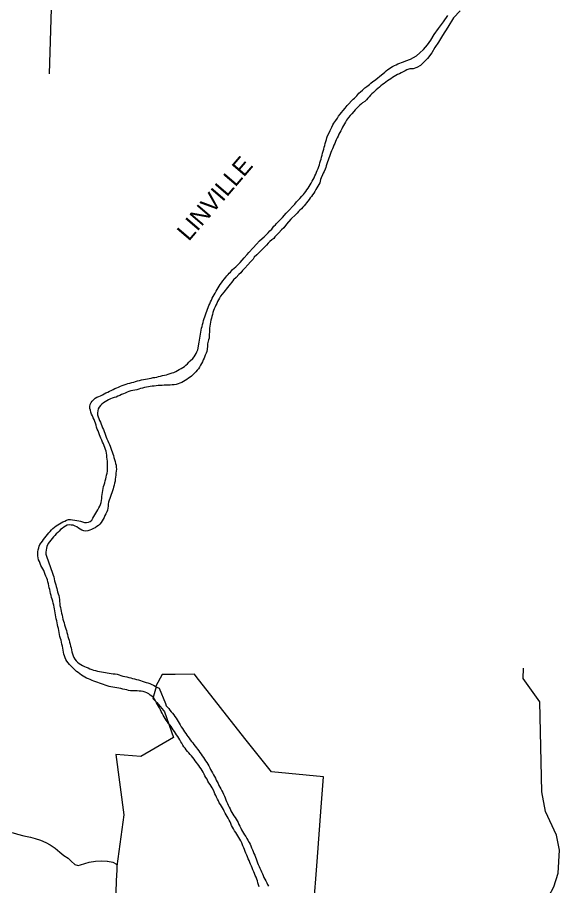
# Model space of a CAD drawing. Extents: x 1113032 to 1302912, y 664689 to 832535.
# Drawn here: x 1135345 to 1141854, y 765901 to 776333 of the extents above; entities that cross this region are included whole.
import ezdxf

# ---------------------------------------------------------------- set-up
doc = ezdxf.new("R2010")
doc.units = 0
for name, color, linetype in [('Exist Boundary Land Use Forest National US Forest Service', 7, 'Continuous'), ('Exist Hydrographic Creek Single Shore', 7, 'Continuous'), ('Exist Hydrographic River Shore', 7, 'Continuous'), ('Exist Hydrographic River Shore Label', 7, 'Continuous'), ('Map Preparation Longitude Latitude Lines', 7, 'Continuous')]:
    doc.layers.add(name, color=color, linetype=linetype)

msp = doc.modelspace()

# ---------------------------------------------------------------- linework, layer by layer
at = {"layer": 'Exist Boundary Land Use Forest National US Forest Service'}
for points in [[(1138713, 763223), (1138723, 763348), (1138943, 766193), (1138993, 766844), (1139021, 767208), (1138394, 767267), (1138077, 767670), (1137491, 768414), (1137470, 768440), (1137238, 768439), (1137082, 768438), (1137008, 768296), (1137011, 768288), (1136972, 768151), (1137018, 768103), (1137101, 768007), (1137113, 767991), (1137220, 767682), (1136825, 767454), (1136525, 767475), (1136621, 766751), (1136539, 766137)], [(1135282, 766541), (1135348, 766518), (1135421, 766500), (1135503, 766483), (1135560, 766467), (1135624, 766449), (1135687, 766421), (1135740, 766390), (1135797, 766350), (1135855, 766304), (1135904, 766264), (1135953, 766231), (1135990, 766197), (1136034, 766154), (1136076, 766145), (1136104, 766152), (1136153, 766166), (1136207, 766182), (1136284, 766194), (1136352, 766198), (1136424, 766195), (1136426, 766195), (1136492, 766183), (1136533, 766158), (1136539, 766137)], [(1136539, 766137), (1136539, 766090), (1136530, 765960), (1136513, 765408), (1136497, 764754), (1136478, 764256), (1136446, 763434), (1136733, 763409), (1136853, 763399), (1137087, 763379), (1137787, 763312), (1138068, 763285), (1138186, 763274), (1138552, 763238), (1138713, 763223)]]:
    msp.add_lwpolyline(points, dxfattribs=at)
at = {"layer": 'Exist Hydrographic Creek Single Shore'}
msp.add_lwpolyline([(1140069, 761301), (1140449, 761951), (1140862, 762655), (1141048, 763042), (1141122, 763273), (1141016, 763659), (1140714, 764161), (1140645, 764353), (1140664, 764720), (1140725, 764811), (1140922, 764964), (1141070, 765191), (1141182, 765297), (1141538, 765487), (1141606, 765551), (1141783, 765889), (1141838, 766052), (1141854, 766328), (1141818, 766506), (1141685, 766791), (1141641, 767028), (1141615, 768111), (1141415, 768391), (1141419, 768516)], dxfattribs=at)
at = {"layer": 'Exist Hydrographic River Shore'}
for points in [[(1140661, 776411), (1140582, 776328), (1140512, 776216), (1140449, 776116), (1140400, 776034), (1140358, 775970), (1140319, 775908), (1140267, 775838), (1140222, 775790), (1140183, 775755), (1140142, 775730), (1140096, 775715), (1140057, 775714), (1140022, 775704), (1140000, 775691), (1139952, 775667), (1139931, 775656), (1139909, 775645), (1139888, 775633), (1139868, 775621), (1139847, 775609), (1139827, 775596), (1139807, 775582), (1139787, 775569), (1139767, 775555), (1139747, 775540), (1139728, 775525), (1139709, 775510), (1139691, 775495), (1139672, 775479), (1139654, 775463), (1139636, 775447), (1139619, 775430), (1139602, 775414), (1139585, 775396), (1139568, 775379), (1139552, 775361), (1139536, 775343), (1139516, 775323), (1139489, 775304), (1139474, 775292), (1139454, 775277), (1139439, 775262), (1139421, 775242), (1139398, 775220), (1139383, 775202), (1139358, 775175), (1139338, 775153)], [(1139028, 774772), (1139035, 774795), (1139041, 774818), (1139048, 774841), (1139055, 774864), (1139061, 774887), (1139068, 774910), (1139086, 774947), (1139100, 774973), (1139118, 775012), (1139133, 775042), (1139144, 775061), (1139168, 775095), (1139186, 775121), (1139200, 775147), (1139219, 775170), (1139235, 775191), (1139255, 775214), (1139279, 775240), (1139305, 775273), (1139320, 775289), (1139358, 775332), (1139376, 775348), (1139390, 775360), (1139418, 775389), (1139445, 775420), (1139463, 775438), (1139487, 775459), (1139515, 775485), (1139539, 775502), (1139557, 775514), (1139573, 775527), (1139588, 775541), (1139614, 775562), (1139632, 775576), (1139667, 775604), (1139695, 775625), (1139733, 775655), (1139755, 775675), (1139773, 775691), (1139791, 775706), (1139811, 775719), (1139830, 775731), (1139850, 775742), (1139871, 775753), (1139892, 775763), (1139914, 775773), (1139935, 775782), (1139957, 775791), (1139980, 775799), (1140010, 775810), (1140066, 775830), (1140101, 775849), (1140138, 775871), (1140178, 775905), (1140221, 775947), (1140267, 776003), (1140310, 776058), (1140348, 776125), (1140401, 776198), (1140461, 776278), (1140514, 776353)], [(1139338, 775153), (1139321, 775128), (1139297, 775096), (1139285, 775075), (1139273, 775055), (1139261, 775034), (1139249, 775013), (1139238, 774992), (1139227, 774971), (1139216, 774949), (1139205, 774928), (1139194, 774906), (1139184, 774885), (1139173, 774863), (1139163, 774841), (1139154, 774819), (1139144, 774797), (1139135, 774775), (1139126, 774753), (1139117, 774731), (1139108, 774709), (1139099, 774686), (1139091, 774663), (1139083, 774641), (1139075, 774618), (1139068, 774595), (1139060, 774573), (1139053, 774550), (1139046, 774527), (1139041, 774507), (1139026, 774479), (1139017, 774460), (1139006, 774441), (1138993, 774403), (1138985, 774386), (1138981, 774364), (1138974, 774346), (1138963, 774325), (1138951, 774304), (1138940, 774283), (1138927, 774263), (1138915, 774242), (1138902, 774222), (1138889, 774202), (1138875, 774182), (1138861, 774163), (1138847, 774143), (1138832, 774124), (1138817, 774105), (1138802, 774087), (1138786, 774069), (1138770, 774051), (1138754, 774033), (1138737, 774016), (1138720, 773999), (1138703, 773982), (1138687, 773966), (1138629, 773908), (1138577, 773847), (1138542, 773806), (1138517, 773779), (1138484, 773743), (1138457, 773717), (1138437, 773694), (1138424, 773677), (1138401, 773659), (1138376, 773638), (1138357, 773619), (1138335, 773594), (1138309, 773569), (1138262, 773525), (1138218, 773481), (1138189, 773453), (1138174, 773429), (1138145, 773397), (1138112, 773361), (1138077, 773321), (1138049, 773291), (1138028, 773263), (1138005, 773242), (1137970, 773209), (1137939, 773181), (1137918, 773153), (1137901, 773129), (1137866, 773086), (1137824, 773033), (1137783, 772982), (1137771, 772961), (1137759, 772940), (1137748, 772919), (1137738, 772897), (1137727, 772876), (1137718, 772854), (1137709, 772831), (1137701, 772809), (1137693, 772786), (1137686, 772763), (1137680, 772740), (1137674, 772717), (1137668, 772693)], [(1137498, 772314), (1137511, 772338), (1137529, 772431), (1137532, 772455), (1137535, 772479), (1137539, 772502), (1137543, 772526), (1137547, 772550), (1137552, 772573), (1137557, 772597), (1137563, 772620), (1137568, 772643), (1137575, 772666), (1137581, 772690), (1137588, 772713), (1137595, 772735), (1137602, 772758), (1137610, 772781), (1137618, 772804), (1137627, 772826), (1137636, 772848), (1137645, 772871), (1137654, 772893), (1137664, 772914), (1137674, 772936), (1137685, 772958), (1137696, 772979), (1137707, 773000), (1137718, 773021), (1137730, 773042), (1137742, 773063), (1137755, 773084), (1137767, 773104), (1137780, 773124), (1137794, 773144), (1137810, 773167), (1137830, 773193), (1137847, 773212), (1137861, 773226), (1137876, 773243), (1137888, 773258), (1137903, 773273), (1137929, 773302), (1137947, 773318), (1137967, 773336), (1137991, 773358), (1138018, 773386), (1138043, 773415), (1138067, 773442), (1138105, 773484), (1138125, 773508), (1138176, 773562), (1138215, 773606), (1138250, 773646), (1138283, 773675), (1138308, 773697), (1138329, 773717), (1138356, 773743), (1138377, 773767), (1138401, 773790), (1138424, 773824), (1138442, 773842), (1138456, 773856), (1138489, 773890), (1138527, 773930), (1138573, 773980), (1138611, 774019), (1138646, 774059), (1138675, 774090), (1138697, 774115), (1138714, 774135), (1138734, 774156), (1138760, 774186), (1138780, 774204), (1138793, 774222), (1138807, 774241), (1138821, 774261), (1138834, 774281), (1138847, 774301), (1138860, 774322), (1138872, 774342), (1138884, 774363), (1138895, 774385), (1138906, 774406), (1138916, 774428), (1138926, 774450), (1138936, 774472), (1138945, 774494), (1138954, 774516), (1138962, 774539), (1138970, 774561), (1138977, 774584), (1138984, 774607), (1138990, 774630), (1138996, 774654), (1139003, 774679), (1139009, 774702), (1139016, 774725), (1139022, 774748), (1139028, 774772)], [(1137668, 772693), (1137664, 772670), (1137660, 772646), (1137656, 772622), (1137653, 772599)], [(1137653, 772599), (1137651, 772575), (1137650, 772551), (1137649, 772527), (1137649, 772503), (1137649, 772479), (1137641, 772460), (1137634, 772443), (1137629, 772411), (1137626, 772382), (1137622, 772348), (1137618, 772317), (1137611, 772300), (1137599, 772273), (1137586, 772239), (1137577, 772217), (1137567, 772195), (1137556, 772173), (1137544, 772153), (1137532, 772132), (1137518, 772112), (1137503, 772093), (1137488, 772075), (1137472, 772057), (1137455, 772041), (1137437, 772024), (1137421, 772011), (1137401, 771997), (1137381, 771983), (1137361, 771970), (1137340, 771958), (1137319, 771947), (1137296, 771939), (1137274, 771930), (1137251, 771923), (1137227, 771919), (1137204, 771916), (1137180, 771912), (1137156, 771912), (1137132, 771913), (1137108, 771913), (1137084, 771911), (1137060, 771909), (1137036, 771908), (1137012, 771905), (1136988, 771902), (1136964, 771900), (1136940, 771898), (1136917, 771894), (1136893, 771890), (1136870, 771884), (1136847, 771878), (1136824, 771872), (1136801, 771865), (1136777, 771859), (1136754, 771853), (1136730, 771849), (1136707, 771844), (1136684, 771837), (1136662, 771828), (1136639, 771819), (1136617, 771809), (1136595, 771800), (1136573, 771790), (1136552, 771780), (1136530, 771770), (1136507, 771764), (1136484, 771756), (1136461, 771748), (1136440, 771736), (1136419, 771725), (1136398, 771714), (1136378, 771701), (1136358, 771687), (1136341, 771670), (1136327, 771651), (1136315, 771630), (1136309, 771606), (1136306, 771583), (1136308, 771559), (1136313, 771535), (1136321, 771513), (1136331, 771491), (1136341, 771469), (1136349, 771446), (1136358, 771424), (1136367, 771402), (1136377, 771380), (1136386, 771358), (1136395, 771336), (1136403, 771313), (1136411, 771290), (1136420, 771268), (1136430, 771246), (1136440, 771225), (1136450, 771203), (1136459, 771180), (1136468, 771158), (1136476, 771135), (1136483, 771113)], [(1136410, 770810), (1136416, 770834), (1136421, 770857), (1136425, 770881), (1136427, 770905), (1136428, 770929), (1136428, 770953), (1136427, 770977), (1136425, 771001), (1136423, 771024), (1136420, 771048), (1136418, 771072), (1136414, 771096), (1136410, 771120), (1136404, 771143), (1136395, 771165), (1136386, 771187), (1136377, 771209), (1136367, 771231), (1136358, 771254), (1136348, 771276), (1136338, 771297), (1136329, 771319), (1136321, 771342), (1136313, 771365), (1136304, 771387), (1136296, 771409), (1136289, 771433), (1136283, 771456), (1136275, 771478), (1136266, 771501), (1136256, 771523), (1136246, 771544), (1136236, 771566), (1136228, 771589), (1136221, 771612), (1136216, 771635), (1136215, 771659), (1136217, 771683), (1136229, 771704), (1136244, 771722), (1136261, 771740), (1136279, 771756), (1136299, 771768), (1136321, 771777), (1136343, 771787), (1136365, 771798), (1136386, 771809), (1136407, 771820), (1136429, 771831), (1136450, 771841), (1136472, 771851), (1136493, 771862), (1136515, 771874), (1136537, 771883), (1136559, 771891), (1136581, 771900), (1136603, 771910), (1136626, 771917), (1136649, 771925), (1136672, 771932), (1136695, 771939), (1136718, 771945), (1136741, 771951), (1136764, 771958), (1136787, 771965), (1136810, 771970), (1136834, 771976), (1136857, 771980), (1136881, 771984), (1136905, 771988), (1136928, 771993), (1136951, 772000), (1136975, 772005), (1136994, 772008), (1137017, 772012), (1137040, 772018), (1137064, 772023), (1137087, 772029), (1137110, 772034), (1137134, 772040), (1137157, 772046), (1137180, 772054), (1137203, 772061), (1137225, 772068), (1137247, 772078), (1137268, 772090), (1137289, 772102), (1137310, 772114), (1137331, 772126), (1137350, 772140), (1137369, 772155), (1137386, 772172), (1137403, 772189), (1137419, 772206), (1137450, 772233), (1137467, 772255), (1137479, 772276), (1137492, 772296), (1137498, 772314)], [(1136483, 771113), (1136491, 771090), (1136498, 771067), (1136504, 771044), (1136510, 771020), (1136517, 770997), (1136523, 770974), (1136529, 770951), (1136531, 770927), (1136533, 770903), (1136531, 770879), (1136528, 770855), (1136526, 770832), (1136523, 770808), (1136520, 770784), (1136517, 770760), (1136512, 770737), (1136506, 770713), (1136500, 770690), (1136494, 770667), (1136486, 770644), (1136479, 770621), (1136471, 770599), (1136464, 770576), (1136456, 770553), (1136446, 770532), (1136439, 770508), (1136436, 770485), (1136434, 770461), (1136431, 770437), (1136425, 770414), (1136418, 770391), (1136408, 770369), (1136396, 770348), (1136386, 770326), (1136375, 770305), (1136363, 770284), (1136350, 770264), (1136335, 770245), (1136317, 770229), (1136298, 770214), (1136278, 770201), (1136257, 770190), (1136235, 770179), (1136213, 770170), (1136190, 770163), (1136166, 770161), (1136142, 770164), (1136120, 770173), (1136098, 770182), (1136079, 770197), (1136059, 770210), (1136037, 770220), (1136016, 770230), (1135991, 770233), (1135967, 770234), (1135944, 770230), (1135922, 770220), (1135901, 770208), (1135881, 770193), (1135863, 770178), (1135846, 770161), (1135829, 770144), (1135812, 770127), (1135794, 770109), (1135777, 770091), (1135761, 770072), (1135745, 770053), (1135730, 770033), (1135716, 770013), (1135700, 769977), (1135693, 769954), (1135689, 769930), (1135686, 769906), (1135688, 769882), (1135695, 769859), (1135704, 769837), (1135712, 769814), (1135720, 769792), (1135728, 769769), (1135735, 769746), (1135743, 769724), (1135750, 769701), (1135757, 769678), (1135765, 769655), (1135774, 769633), (1135781, 769610), (1135785, 769586), (1135790, 769563), (1135798, 769540), (1135805, 769517), (1135811, 769494), (1135818, 769471), (1135823, 769452), (1135828, 769432), (1135835, 769409), (1135841, 769386), (1135846, 769363), (1135849, 769339), (1135852, 769315)], [(1136388, 770717), (1136394, 770740), (1136399, 770764), (1136405, 770787), (1136410, 770810)], [(1135863, 768872), (1135856, 768895), (1135851, 768919), (1135846, 768942), (1135842, 768966), (1135837, 768990), (1135832, 769013), (1135827, 769036), (1135822, 769060), (1135817, 769083), (1135812, 769107), (1135808, 769130), (1135803, 769154), (1135798, 769177), (1135794, 769201), (1135791, 769225), (1135786, 769248), (1135781, 769272), (1135775, 769295), (1135769, 769318), (1135762, 769341), (1135756, 769364), (1135749, 769388), (1135743, 769411), (1135738, 769435), (1135733, 769458), (1135728, 769481), (1135724, 769505), (1135719, 769528), (1135712, 769551), (1135705, 769574), (1135697, 769597), (1135687, 769618), (1135679, 769641), (1135671, 769664), (1135661, 769686), (1135649, 769707), (1135638, 769728), (1135628, 769749), (1135618, 769771), (1135609, 769794), (1135600, 769816), (1135594, 769839), (1135590, 769863), (1135589, 769887), (1135591, 769911), (1135596, 769934), (1135602, 769958), (1135608, 769981), (1135615, 769999), (1135631, 770019), (1135645, 770038), (1135659, 770060), (1135674, 770081), (1135689, 770101), (1135705, 770121), (1135722, 770139), (1135739, 770157), (1135755, 770175), (1135771, 770192), (1135789, 770209), (1135809, 770222), (1135829, 770235), (1135849, 770248), (1135869, 770261), (1135891, 770272), (1135913, 770281), (1135935, 770291), (1135957, 770300), (1135981, 770299), (1136005, 770295), (1136034, 770292), (1136057, 770289), (1136081, 770285), (1136104, 770279), (1136127, 770271), (1136151, 770266), (1136175, 770266), (1136199, 770268), (1136220, 770278), (1136238, 770294), (1136250, 770315), (1136261, 770336), (1136273, 770357), (1136285, 770378), (1136298, 770398), (1136311, 770418), (1136322, 770439), (1136336, 770459), (1136344, 770482), (1136350, 770505), (1136354, 770529), (1136357, 770552), (1136359, 770576), (1136362, 770600), (1136366, 770624), (1136370, 770648), (1136374, 770671), (1136379, 770695), (1136388, 770717)], [(1135852, 769315), (1135854, 769291), (1135856, 769267), (1135861, 769244), (1135867, 769220), (1135872, 769197), (1135876, 769173), (1135881, 769150), (1135887, 769126), (1135892, 769103), (1135898, 769080), (1135905, 769057), (1135912, 769034), (1135919, 769011), (1135927, 768988), (1135933, 768965), (1135940, 768942), (1135945, 768919), (1135950, 768895), (1135957, 768872), (1135965, 768850), (1135972, 768826), (1135978, 768803), (1135984, 768780), (1135989, 768757), (1135995, 768733), (1136000, 768710), (1136005, 768686), (1136013, 768664), (1136022, 768642), (1136035, 768621), (1136051, 768603), (1136068, 768586), (1136086, 768571), (1136106, 768557), (1136127, 768545), (1136149, 768536), (1136171, 768527), (1136193, 768517), (1136215, 768507), (1136237, 768498), (1136260, 768490), (1136283, 768484), (1136306, 768478), (1136330, 768474), (1136354, 768470), (1136378, 768467), (1136401, 768462), (1136424, 768456), (1136448, 768452), (1136472, 768449), (1136496, 768447), (1136520, 768445), (1136543, 768442), (1136566, 768435), (1136588, 768426), (1136611, 768419), (1136635, 768414), (1136658, 768408), (1136681, 768402), (1136705, 768396), (1136728, 768390), (1136751, 768384), (1136775, 768378), (1136798, 768373), (1136821, 768365), (1136843, 768357), (1136866, 768350), (1136889, 768343), (1136912, 768336), (1136935, 768328), (1136957, 768319), (1136979, 768309), (1137000, 768298), (1137020, 768285), (1137048, 768272), (1137122, 768088), (1137133, 768063), (1137148, 768047), (1137162, 768028), (1137177, 768009), (1137193, 767990), (1137208, 767972), (1137222, 767953), (1137237, 767933), (1137250, 767914), (1137263, 767894), (1137276, 767873), (1137288, 767852), (1137300, 767832), (1137313, 767811), (1137326, 767791), (1137340, 767771), (1137353, 767751), (1137366, 767731), (1137379, 767711), (1137393, 767692), (1137407, 767672), (1137421, 767653), (1137436, 767634)], [(1137494, 767382), (1137480, 767402), (1137466, 767422), (1137451, 767441), (1137436, 767459), (1137421, 767478), (1137405, 767496), (1137389, 767514), (1137373, 767532), (1137358, 767551), (1137345, 767570), (1137331, 767590), (1137319, 767611), (1137307, 767631), (1137295, 767653), (1137283, 767673), (1137270, 767694), (1137257, 767714), (1137243, 767733), (1137230, 767753), (1137217, 767773), (1137204, 767794), (1137191, 767814), (1137177, 767833), (1137161, 767851), (1137146, 767870), (1137132, 767889), (1137118, 767909), (1137107, 767930), (1137095, 767951), (1137084, 767972), (1137072, 767994), (1137062, 768015), (1137052, 768037), (1137039, 768057), (1137027, 768078), (1137016, 768099), (1137004, 768120), (1136992, 768141), (1136977, 768160), (1136959, 768176), (1136940, 768191), (1136922, 768206), (1136900, 768216), (1136878, 768224), (1136855, 768232), (1136831, 768237), (1136807, 768239), (1136784, 768241), (1136752, 768242), (1136727, 768242), (1136703, 768243), (1136680, 768247), (1136657, 768253), (1136633, 768259), (1136610, 768263), (1136586, 768268), (1136563, 768273), (1136539, 768277), (1136516, 768282), (1136492, 768285), (1136468, 768289), (1136445, 768295), (1136422, 768302), (1136399, 768309), (1136377, 768318), (1136354, 768325), (1136331, 768333), (1136309, 768342), (1136286, 768350), (1136264, 768359), (1136241, 768367), (1136219, 768376), (1136197, 768385), (1136175, 768395), (1136154, 768405), (1136133, 768418), (1136113, 768431), (1136093, 768445), (1136074, 768460), (1136056, 768475), (1136038, 768491), (1136021, 768508), (1136004, 768525), (1135988, 768543), (1135971, 768560), (1135955, 768578), (1135940, 768597), (1135927, 768617), (1135917, 768639), (1135909, 768661), (1135902, 768684), (1135897, 768708), (1135893, 768732), (1135889, 768755), (1135885, 768779), (1135880, 768802), (1135875, 768826), (1135869, 768849), (1135863, 768872)], [(1137436, 767634), (1137450, 767615), (1137465, 767596), (1137480, 767577), (1137494, 767558), (1137509, 767539), (1137523, 767519), (1137537, 767500), (1137551, 767481), (1137565, 767461), (1137579, 767441), (1137592, 767421), (1137605, 767401), (1137619, 767381), (1137631, 767361), (1137643, 767339), (1137654, 767318), (1137665, 767297), (1137677, 767276), (1137688, 767255), (1137700, 767234), (1137711, 767213), (1137722, 767191), (1137732, 767170), (1137743, 767148), (1137754, 767127), (1137765, 767105), (1137776, 767084), (1137788, 767063), (1137800, 767042), (1137811, 767021), (1137821, 767000), (1137830, 766977), (1137839, 766955), (1137848, 766933), (1137857, 766911), (1137867, 766889), (1137877, 766867), (1137887, 766845), (1137898, 766824), (1137908, 766802), (1137920, 766781), (1137932, 766760), (1137945, 766740), (1137958, 766720), (1137971, 766700), (1137983, 766679), (1137995, 766658), (1138005, 766636), (1138015, 766615), (1138026, 766593), (1138036, 766572), (1138048, 766551), (1138060, 766530), (1138073, 766510), (1138086, 766490), (1138099, 766469), (1138111, 766449), (1138127, 766421), (1138139, 766400), (1138148, 766378), (1138156, 766355), (1138166, 766333), (1138175, 766311), (1138185, 766289), (1138195, 766267), (1138203, 766245), (1138211, 766222), (1138220, 766200), (1138228, 766177), (1138237, 766155), (1138247, 766133), (1138257, 766111), (1138267, 766089), (1138277, 766068), (1138286, 766045), (1138295, 766023), (1138305, 766001), (1138316, 765980), (1138327, 765959), (1138338, 765937), (1138349, 765916), (1138359, 765894)], [(1138246, 765889), (1138240, 765912), (1138233, 765935), (1138228, 765959), (1138220, 765981), (1138211, 766004), (1138201, 766025), (1138191, 766047), (1138182, 766069), (1138173, 766092), (1138163, 766114), (1138154, 766136), (1138145, 766158), (1138137, 766181), (1138127, 766203), (1138117, 766225), (1138108, 766247), (1138098, 766269), (1138089, 766291), (1138080, 766313), (1138071, 766335), (1138062, 766357), (1138053, 766380), (1138039, 766417), (1138029, 766439), (1138017, 766460), (1138004, 766480), (1137992, 766501), (1137979, 766521), (1137966, 766541), (1137953, 766561), (1137941, 766582), (1137929, 766603), (1137917, 766624), (1137907, 766646), (1137898, 766668), (1137888, 766689), (1137876, 766711), (1137865, 766732), (1137853, 766753), (1137841, 766774), (1137829, 766795), (1137818, 766815), (1137806, 766836), (1137794, 766857), (1137782, 766878), (1137769, 766898), (1137758, 766919), (1137747, 766941), (1137737, 766963), (1137727, 766984), (1137717, 767006), (1137707, 767028), (1137698, 767050), (1137684, 767078), (1137671, 767098), (1137658, 767118), (1137645, 767138), (1137632, 767158), (1137622, 767180), (1137609, 767200), (1137597, 767221), (1137586, 767242), (1137575, 767263), (1137562, 767284), (1137550, 767305), (1137537, 767325), (1137522, 767344), (1137508, 767363), (1137494, 767382)]]:
    msp.add_lwpolyline(points, dxfattribs=at)
at = {"layer": 'Map Preparation Longitude Latitude Lines'}
msp.add_line((1135732, 775655), (1136118, 788801), dxfattribs=at)

# ---------------------------------------------------------------- texts
at = {"layer": 'Exist Hydrographic River Shore Label'}
msp.add_text('LINVILLE', height=210, rotation=49.427, dxfattribs=at).set_placement((1137402, 773634))

doc.saveas('drawing.dxf')
